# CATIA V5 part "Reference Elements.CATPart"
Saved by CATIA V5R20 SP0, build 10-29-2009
Part number: Part1
Bounding box of the stored display mesh (mm): x -435 to 853, y -947.026 to 1464.599, z -975.819 to 506.423
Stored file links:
  G:\카티아자료\수업자료\툴바예제\2 PartDesign\part design_refereneces.CATPart
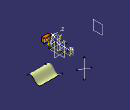
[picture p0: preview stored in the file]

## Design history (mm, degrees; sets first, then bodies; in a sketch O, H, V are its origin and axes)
AxisSystem1: origin (71, -219.286, 472.544), X (0, 250.28, -101.015), Y (0, -0.3743, -0.9273), Z (-1, 0, 0)
Set1
  Plane1: type Offset, RefPlane yz-plane, Offset -1681
  Sketch1 on yz-plane, origin (0, 0, 0), H (0, 1, 0), V (0, 0, 1)
    spline S1 through (-604.696, -855.9429) (-363.4818, -755.3875) (-152.4194, -956.4983) (98.8453, -855.9429)
  Extrude1: Lim1 853, Lim2 0, Element1 Sketch1
Body1 (main body)
  Sketch2 on yz-plane, origin (0, 0, 0), H (0, 1, 0), V (0, 0, 1)
    line L1 (162.4189, -5.3979) -> (241.5494, -5.3979)
    line L2 (241.5494, -5.3979) -> (241.5494, 51.1517)
    line L3 (241.5494, 51.1517) -> (162.4189, 51.1517)
    line L4 (162.4189, 51.1517) -> (162.4189, -5.3979)
    horizontal: L1 H, L3 H
    vertical: L2 V, L4 V
  Pad1: profile Sketch2, direction (1, 0, 0), length 20
  Translate1: Direction yz-plane, Length 71, ToTransfor Pad1
  Sketch3 on start face of Pad1, origin (71, 0, 0), H (0, -1, 0), V (0, 0, 1)
    spline S1 through (-385.0035, 181.1497) (-241.5433, 274.2272) (-125.4709, 148.0941) (4.078, 281.1863) (84.0679, 291.19)
  Plane2: type 1Curve, Element1 Sketch3
  Sketch4 on Plane2, origin (71, 0, 0), H (0, -1, 0), V (0, 0, 1)
    circle A1 centre (-589.0945, 363.2828) radius 50
    radius A1 = 50
  Sketch5 on Plane2, origin (71, 0, 0), H (0, -1, 0), V (0, 0, 1)
    arc A1 centre (-284.0915, 403.8011) radius 102.6563 from (-186.9312, 436.9402) to (-366.3538, 465.2115) ccw
  Point1: type OnPlane, Support Plane2, H 219.286, V 472.544, Direction (0, -1, 0)
  Point2: type OnPlane, Support Plane2, H 240.566, V 304.561, Direction (0, -1, 0)
Body2
  Sketch6, origin (135, -337.1789, 89.2255), H (0, 1, 0), V (0, 0, -1)
    line L1 (84.0268, 0) -> (0, 0)
    line L2 (0, 0) -> (0, 147.1193)
    line L3 (0, 147.1193) -> (84.0268, 147.1193)
    line L4 (84.0268, 147.1193) -> (84.0268, 0)
  Pad2: profile Sketch6, direction along , length 285
Body3
  Sketch7, origin (135, -640.0256, -73.6566), H (0, 1, 0), V (0, 0, -1)
    line L1 (0, 0) -> (0, -173.3906)
    line L2 (0, 0) -> (127.7908, 0)
    line L3 (127.7908, -173.3906) -> (127.7908, 0)
    line L4 (127.7908, -173.3906) -> (0, -173.3906)
  Pad3: profile Sketch7, direction along , length 285
  Translate2: Direction edge [face of Pad3 from Sketch7.L2 | end face of Pad3], Length 307, ToTransfor Pad3
  Point3: type OnPlane, Support face of Pad3 from Sketch7.L2, H -158.673, V 708.809, Direction (1, 0, 0)
  Point4: type OnPlane, Support face of Pad2 from Sketch6.L3, H -110.768, V 437.996, Direction (1, 0, 0)
  Affinity1: AxisOrigin vertex [face of Pad3 from Sketch7.L2 | end face of Pad3 | face of Pad3 from Sketch7.L1], AxisPlane end face of Pad3, AxisFirstDirection edge [face of Pad3 from Sketch7.L2 | end face of Pad3], RatioX 1, RatioY -1, RatioZ -1, ToTransfor Translate2
  Point5: type OnPlane, Support Plane2, H -30.994, V 371.529, Direction (0, -1, 0)
  Point6: type OnPlane, Support zx-plane, H 98.827, V 10.297, Direction (-1, 0, 0)
  Sketch8 on Plane2, origin (71, 0, 0), H (0, -1, 0), V (0, 0, 1)
    line L1 (-1150.0752, -514.9763) -> (-1150.0752, 300.1915)
    line L2 (-1464.5991, 72.4241) -> (-847.5332, -308.1874)
    vertical: L1 V
  DatumCurve1
  DatumCurve2
  Point7: type Center, Curve Sketch4
  Point8: type OnPlane, Support Plane2, H -580.135, V 173.159, Direction (0, -1, 0)
  Line1: type Bisecting, Element1 DatumCurve2, Element2 DatumCurve1, RefPoint Point3, Support face of Pad3 from Sketch7.L3, Start 267, End -273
